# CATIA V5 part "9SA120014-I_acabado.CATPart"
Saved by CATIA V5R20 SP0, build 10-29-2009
Part number: 9SA120014-I_acabado
Revision: ANY
Definition: UNKNOWN
Nomenclature: 9SA120014-I_acabado
Source: Unknown
Bounding box of the stored display mesh (mm): x -3.519 to 3.519, y -12 to 3, z -3.7 to 3.7
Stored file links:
  C:\Users\Utente\Desktop\IO LAVORO\3D X SITO CF\CUMSA\3D files SA\SA 120014\9SA120014-I_acabado.CATPart
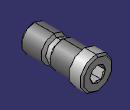
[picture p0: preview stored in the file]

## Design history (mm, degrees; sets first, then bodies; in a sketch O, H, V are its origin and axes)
Body1 "Cortar-Extruir1" (main body)
  Solid1: solid without history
